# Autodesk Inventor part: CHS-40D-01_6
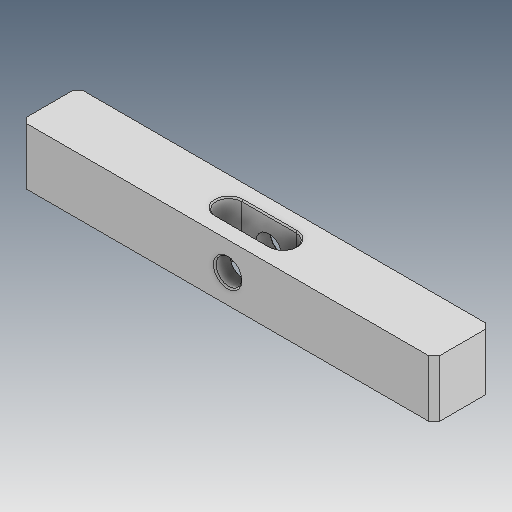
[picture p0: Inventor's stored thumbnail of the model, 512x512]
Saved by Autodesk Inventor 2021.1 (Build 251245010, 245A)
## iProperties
Created: 2019-04
Part Number: CHS-40D-01_6
Material: Ogólny
Document SubType Name: Modeling
Designer: user
Density: 1 g/cm^3
Appearance: Domyślna
Author: user
Revision Number: ÈÎºÎ
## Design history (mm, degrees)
feature "ÊäÈë1"
node "Bryła1"
